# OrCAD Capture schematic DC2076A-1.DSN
size Custom
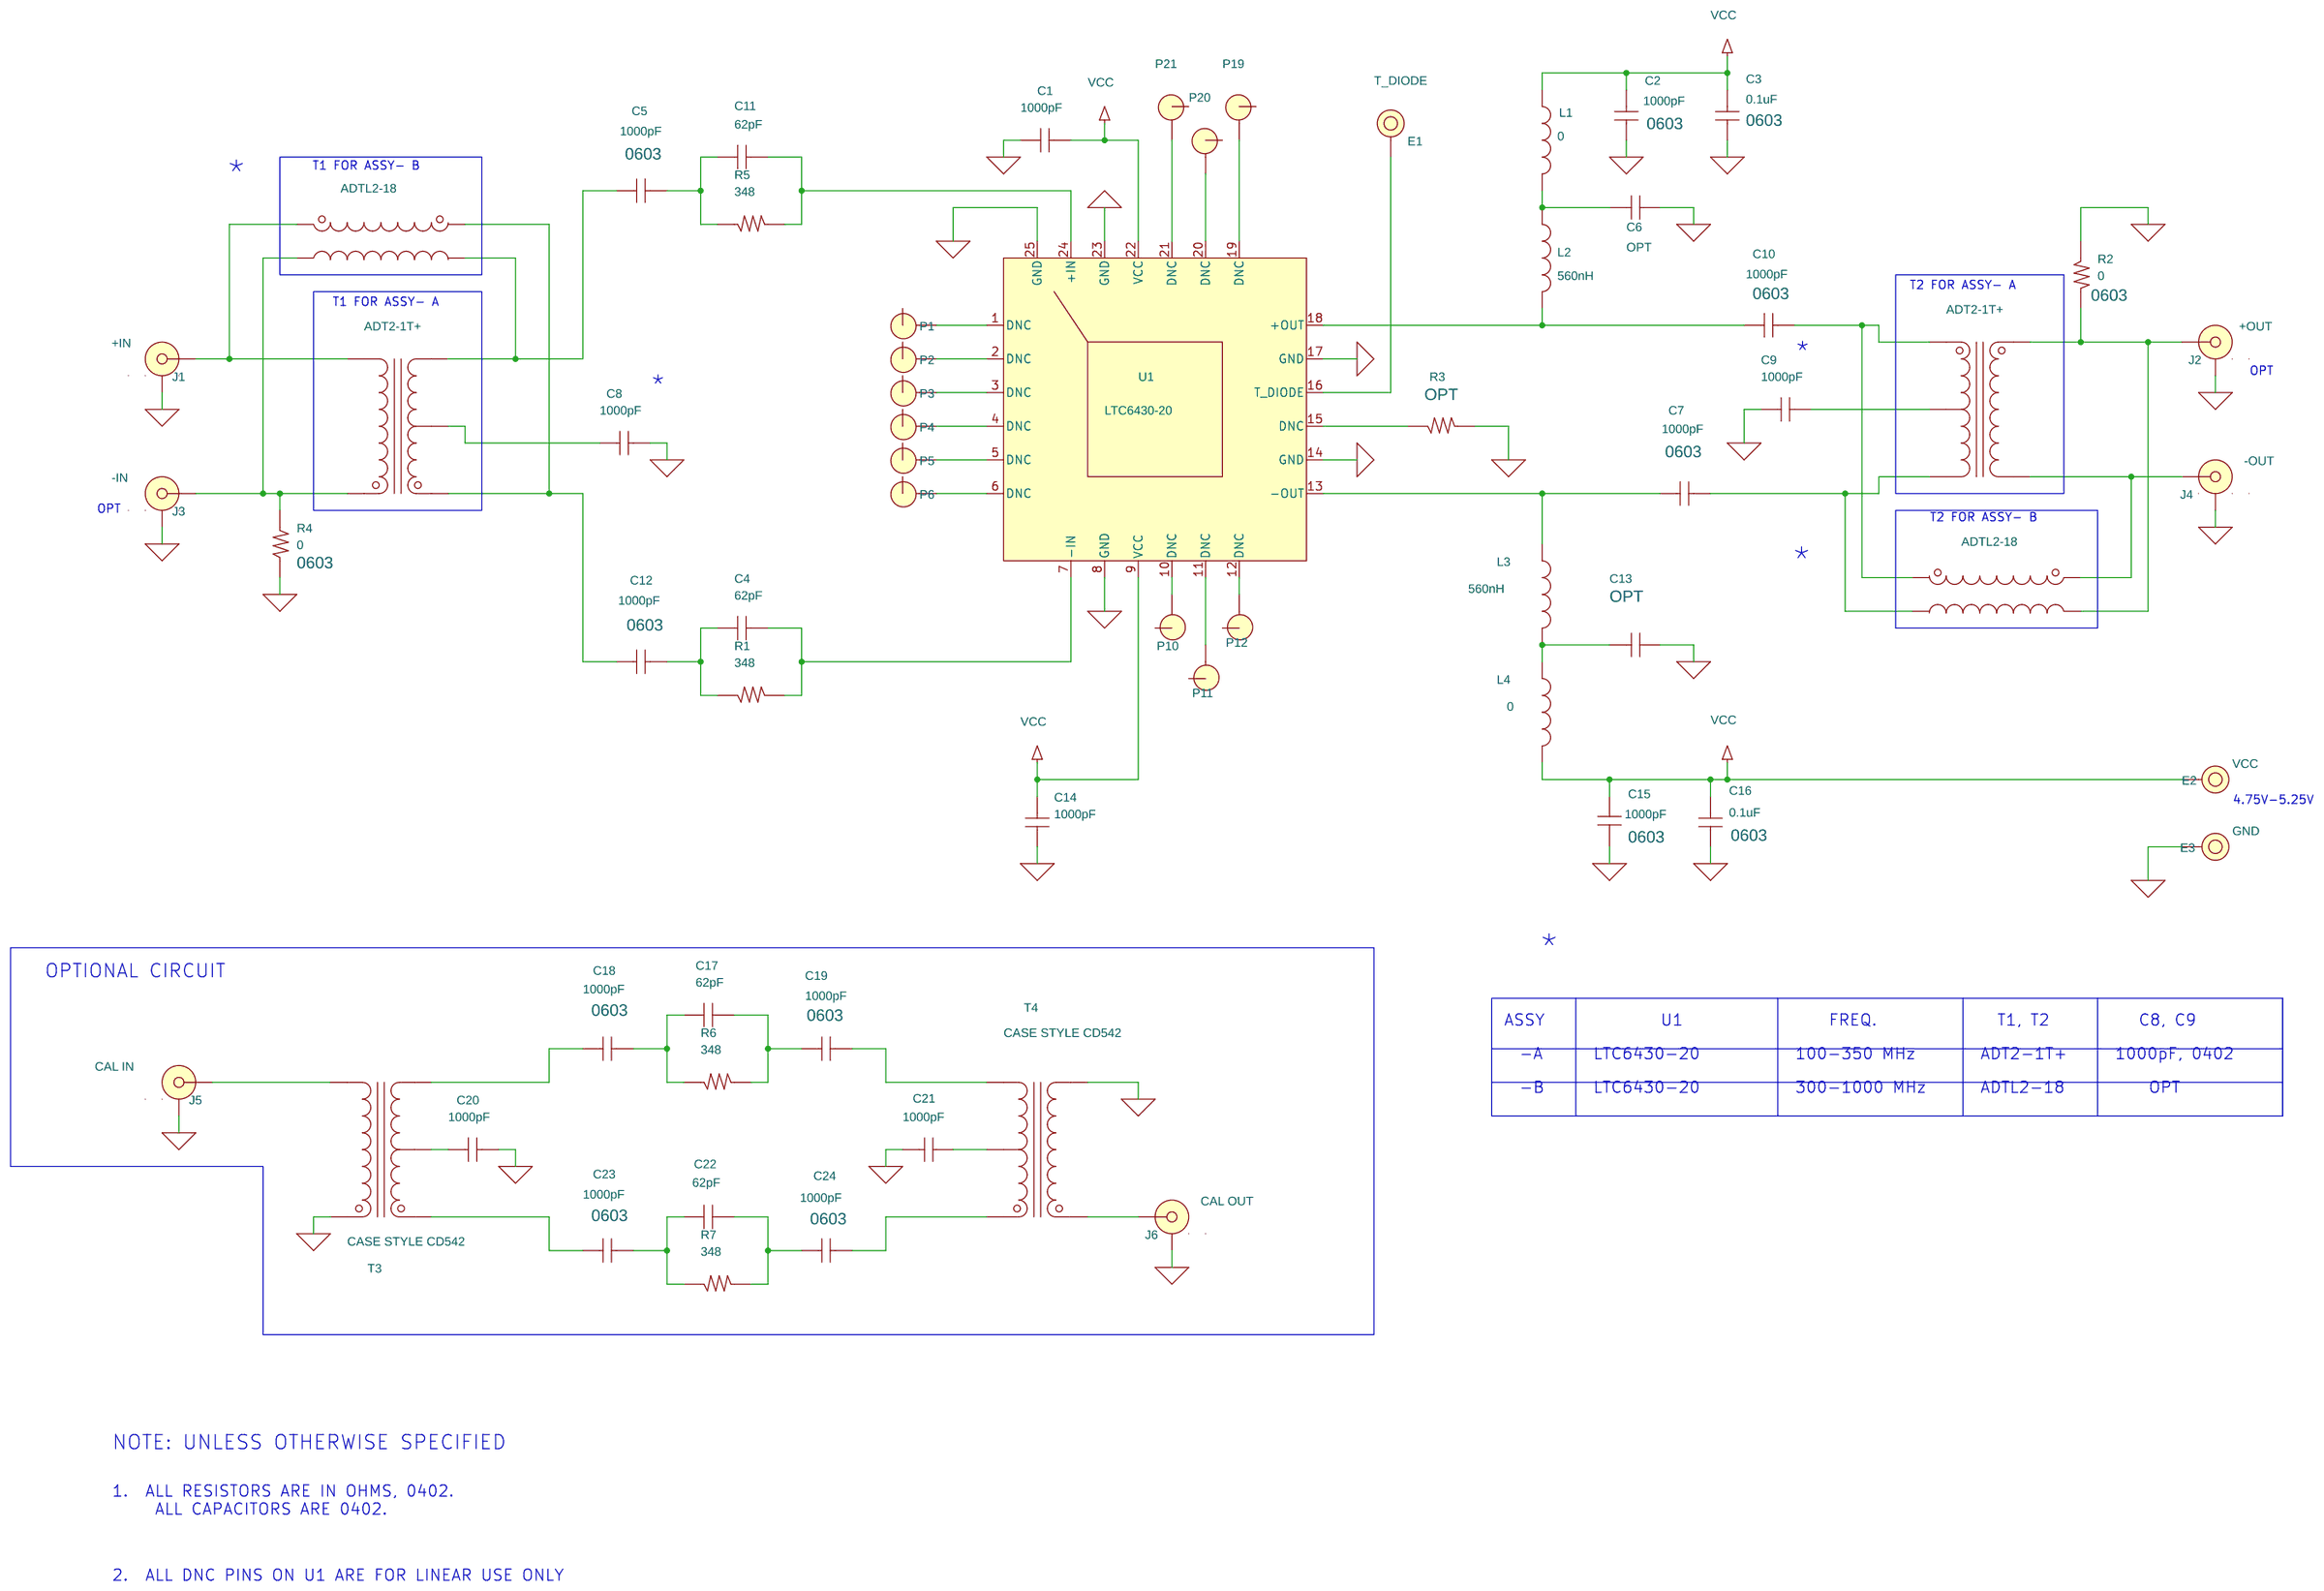
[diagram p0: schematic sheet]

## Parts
C1  1000pF  [0402]
C2  1000pF  [0603]
C3  0.1uF  [0603]
C4  62pF  [0402]
C5  1000pF  [0603]
C6  OPT  [0603]
C7  1000pF  [0603]
C8  1000pF  [0402]
C9  1000pF  [0402]
C10  1000pF  [0603]
C11  62pF  [0402]
C12  1000pF  [0603]
C13  OPT  [0603]
C14  1000pF  [0402]
C15  1000pF  [0603]
C16  0.1uF  [0603]
C17  62pF  [0402]
C18  1000pF  [0603]
C19  1000pF  [0603]
C20  1000pF  [0402]
C21  1000pF  [0402]
C22  62pF  [0402]
C23  1000pF  [0603]
C24  1000pF  [0603]
E1  T_DIODE  [MM/2501]
E2  VCC  [MM/2501]
E3  GND  [MM/2501]
J1  +IN  [CON\SMA-END]
J2  +OUT  [CON\SMA-END]
J3  -IN  [CON\SMA-END]
J4  -OUT  [CON\SMA-END]
J5  CAL IN  [CON\SMA-END]
J6  CAL OUT  [CON\SMA-END]
L1  0  [L-0603LS-1608]
L2  560nH  [L-0603LS-1608]
L3  560nH  [L-0603LS-1608]
L4  0  [L-0603LS-1608]
P1  T/H-PAD  [PAD-15X30]
P2  T/H-PAD  [PAD-15X30]
P3  T/H-PAD  [PAD-15X30]
P4  T/H-PAD  [PAD-15X30]
P5  T/H-PAD  [PAD-15X30]
P6  T/H-PAD  [PAD-15X30]
P10  T/H-PAD  [PAD-15X30]
P11  T/H-PAD  [PAD-15X30]
P12  T/H-PAD  [PAD-15X30]
P19  T/H-PAD  [PAD-15X30]
P20  T/H-PAD  [PAD-15X30]
P21  T/H-PAD  [PAD-15X30]
R1  348  [0402]
R2  0  [0603]
R3  R-0402  [0402]
R4  0  [0603]
R5  348  [0402]
R6  348  [0402]
R7  348  [0402]
T1  ADT2-1T+  [TRANS-CD542]
T2  ADT2-1T+  [TRANS-CD542]
T3  CASE STYLE CD542  [TRANS-CD542]
T4  CASE STYLE CD542  [TRANS-CD542]
T10  ADTL2-18  [TRANS-CD542]
T20  ADTL2-18  [TRANS-CD542]
U1  LTC6430-20  [QFN24UF-4X4]

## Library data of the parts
C1-C24 = CAP-NP
E1-E3 = CON_KEY_575-4_0
J1-J6 = CON_SMA-END_3: CONN, BNC, SMA 50-OHM EDGE-LANCH; 1 FILD: 50 Ohm; 2 FILD: 30MHz-3000MHz; Part Number: E.F.JOHNSON, 142-0701-851
L1-L4 = INDUCTOR
P1-P6 P10-P12 P19-P21 = T_H-PAD_0
R1 R2 R4-R7 = R
R3 = R: 1st Part Field: 0; OPT: OPT
T1-T4 = TRANS-MINI-ADT2-1T_0
T10 = TRANS-MINI-ADT2-1T_5
T20 = TRANS-MINI-ADT2-1T_6
U1 = LTC643XCUF-QFN24UF-4X4_5

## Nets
GND: C1.1 C2.1 C3.1 C6.1 C8.2 C9.1 C13.1 C14.1 C15.2 C16.1 C20.2 C21.2 E3.1 J1.2(GND) J1.3(GND) J1.4(GND) J1.5(GND) J2.2(GND) J2.3(GND) J2.4(GND) J2.5(GND) J3.2(GND) J3.3(GND) J3.4(GND) J3.5(GND) J4.2(GND) J4.3(GND) J4.4(GND) J4.5(GND) J5.2(GND) J5.3(GND) J5.4(GND) J5.5(GND) J6.2(GND) J6.3(GND) J6.4(GND) J6.5(GND) R2.1 R3.2 R4.1 T3.3 T4.1 U1.8(GND) U1.14(GND) U1.17(GND) U1.23(GND) U1.25(GND)
VCC: C1.2 C2.2 C3.2 C14.2 C15.1 C16.2 E2.1 L1.2 L4.2 U1.9(VCC) U1.22(VCC)
N16960429: R3.1 U1.15(DNC)
N16960500: C7.1 L3.1 U1.13(-OUT)
N16960505: C10.2 T2.6 T20.6
N16960519: C8.1 T1.5
N16960665: C4.2 R1.2 U1.7(-IN)
N16960683: J3.1(CENTER) R4.2 T1.3 T10.3
N16960982: C5.2 C11.1 R5.1
N16960990: C12.1 T1.6 T10.6
N16960992: C4.1 C12.2 R1.1
N16961027: C11.2 R5.2 U1.24(+IN)
N16961165: P21.1 U1.21(DNC)
N16961179: P20.1 U1.20(DNC)
N16961189: P19.1 U1.19(DNC)
N16961199: E1.1 U1.16(T_DIODE)
N16977677: C9.2 T2.5
N17087959: C10.1 L2.1 U1.18(+OUT)
N17183335: C5.1 T1.4 T10.4
N17574599: P1.1 U1.1(DNC)
N17574879: P2.1 U1.2(DNC)
N17575161: P3.1 U1.3(DNC)
N17575445: P4.1 U1.4(DNC)
N17575731: P5.1 U1.5(DNC)
N17576019: P6.1 U1.6(DNC)
N17634063: C6.2 L1.1 L2.2
N17634473: C13.2 L3.2 L4.1
N17652021: C22.2 C24.1 R7.2
N17652026: J5.1(CENTER) T3.1
N17652028: C17.2 C19.1 R6.2
N17652032: C19.2 T4.4
N17652103: C18.1 T3.4
N17652105: C17.1 C18.2 R6.1
N17652121: C23.1 T3.6
N17652123: C22.1 C23.2 R7.1
N17652179: C24.2 T4.6
N17652211: C21.1 T4.5
N17652213: C20.1 T3.5
N17652234: J6.1(CENTER) T4.3
N17661728: P10.1 U1.10(DNC)
N17661948: P11.1 U1.11(DNC)
N17662170: P12.1 U1.12(DNC)
N17677180: C7.2 T2.4 T20.4
N17677189: J2.1(CENTER) R2.2 T2.3 T20.3
N17700965: J1.1(CENTER) T1.1 T10.1
N17711989: J4.1(CENTER) T2.1 T20.1

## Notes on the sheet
- *
- T1 FOR ASSY- B
- T2 FOR ASSY- A
- T1 FOR ASSY- A
- *
- OPT
- *
- OPT
- T2 FOR ASSY- B
- *
- 4.75V-5.25V
- *
- OPTIONAL CIRCUIT
- ASSY
- U1
- FREQ.
- T1, T2
- C8, C9
- -A
- LTC6430-20
- 100-350 MHz
- ADT2-1T+
- 1000pF, 0402
- -B
- LTC6430-20
- 300-1000 MHz
- ADTL2-18
- OPT
- NOTE: UNLESS OTHERWISE SPECIFIED
- 1.  ALL RESISTORS ARE IN OHMS, 0402.
       ALL CAPACITORS ARE 0402.
- 2.  ALL DNC PINS ON U1 ARE FOR LINEAR USE ONLY
